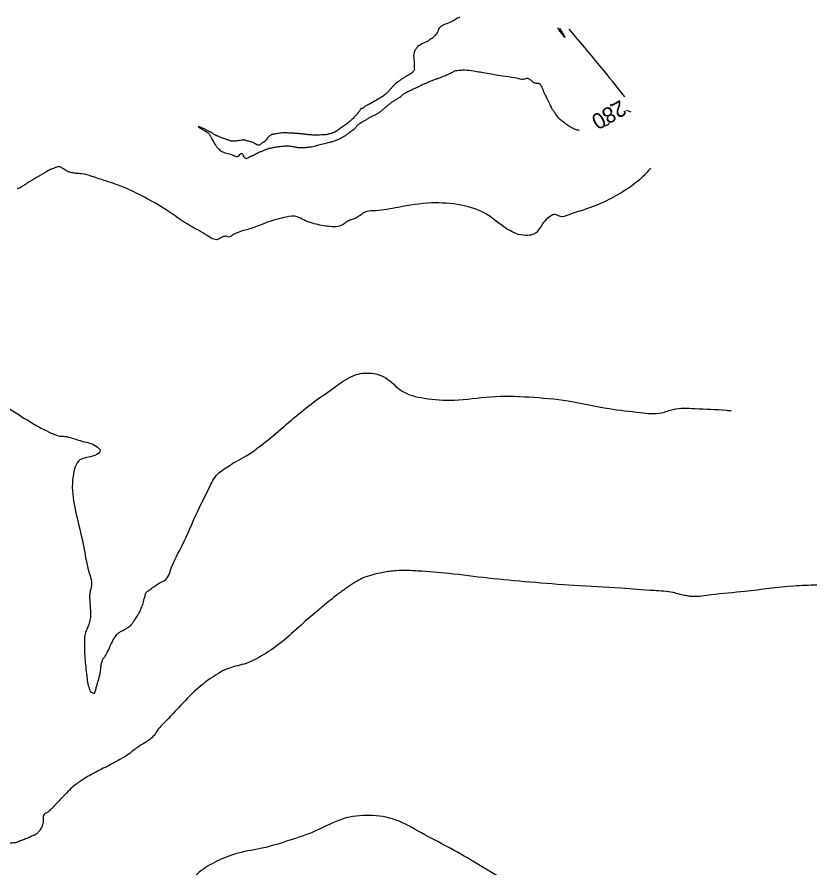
# Model space of a CAD drawing. Extents: x -478102 to -473059, y -1117705 to -1114104.
# Drawn here: x -473729.7 to -473526.4, y -1114945.8 to -1114729.7 of the extents above; entities that cross this region are included whole.
import ezdxf

# ---------------------------------------------------------------- set-up
doc = ezdxf.new("R2010")
doc.units = 0
for name, color, linetype in [('Vrstevnice_hlavni', 7, 'Continuous'), ('Vrstevnice_popis', 7, 'Continuous'), ('Vrstevnice_vedlejsi', 7, 'Continuous')]:
    doc.layers.add(name, color=color, linetype=linetype)

msp = doc.modelspace()

# ---------------------------------------------------------------- linework, layer by layer
at = {"layer": 'Vrstevnice_hlavni'}
msp.add_line((-473574.83, -1114753.395), (-473573.679, -1114753.827), dxfattribs=at)
for points in [[(-473617.201, -1114729.697), (-473620.148, -1114731.265), (-473622.556, -1114732.781), (-473622.788, -1114733.415), (-473623.112, -1114733.992), (-473623.528, -1114734.514), (-473624.036, -1114734.979), (-473624.873, -1114735.541), (-473626.039, -1114736.199), (-473627.533, -1114736.953), (-473628.485, -1114738.067), (-473628.894, -1114739.541), (-473628.762, -1114741.376), (-473628.733, -1114742.663), (-473628.81, -1114743.403), (-473628.991, -1114743.596), (-473629.151, -1114743.75), (-473629.289, -1114743.864), (-473629.405, -1114743.939), (-473629.727, -1114744.134), (-473630.256, -1114744.448), (-473630.99, -1114744.883), (-473631.672, -1114745.321), (-473632.303, -1114745.763), (-473632.882, -1114746.208), (-473633.327, -1114746.553), (-473633.638, -1114746.797), (-473633.816, -1114746.94), (-473634.103, -1114747.235), (-473634.498, -1114747.683), (-473635.003, -1114748.283), (-473635.499, -1114748.811), (-473635.985, -1114749.268), (-473636.461, -1114749.652), (-473637.345, -1114750.232), (-473638.637, -1114751.007), (-473640.337, -1114751.976), (-473641.474, -1114752.622), (-473642.048, -1114752.942), (-473642.058, -1114752.938), (-473642.093, -1114752.94), (-473642.151, -1114752.948), (-473642.234, -1114752.961), (-473642.292, -1114752.989), (-473642.327, -1114753.032), (-473642.336, -1114753.09), (-473642.459, -1114753.28), (-473642.694, -1114753.604), (-473643.042, -1114754.06), (-473643.374, -1114754.477), (-473643.691, -1114754.855), (-473643.992, -1114755.193), (-473644.356, -1114755.56), (-473644.781, -1114755.954), (-473645.268, -1114756.376), (-473645.75, -1114756.766), (-473646.226, -1114757.123), (-473646.697, -1114757.448), (-473647.191, -1114757.792), (-473647.706, -1114758.157), (-473648.243, -1114758.541), (-473648.704, -1114758.835), (-473649.087, -1114759.038), (-473649.394, -1114759.152), (-473649.692, -1114759.255), (-473649.983, -1114759.35), (-473650.264, -1114759.434), (-473650.592, -1114759.51), (-473650.965, -1114759.576)], [(-473591.822, -1114732.544), (-473591.728, -1114732.694), (-473590.442, -1114734.872), (-473591.739, -1114733.259), (-473592.29, -1114732.491)], [(-473575.227, -1114749.998), (-473580.407, -1114743.505), (-473589.357, -1114732.82)], [(-473622.72, -1114745.287), (-473622.568, -1114745.267), (-473622.091, -1114745.085), (-473621.287, -1114744.741), (-473620.158, -1114744.236), (-473619.302, -1114743.843), (-473618.719, -1114743.561), (-473618.41, -1114743.39), (-473617.847, -1114743.267), (-473617.031, -1114743.19), (-473615.96, -1114743.159), (-473613.701, -1114743.412), (-473610.254, -1114743.949), (-473605.617, -1114744.769), (-473602.401, -1114745.262), (-473600.606, -1114745.428), (-473600.23, -1114745.267), (-473599.808, -1114745.309), (-473599.338, -1114745.554), (-473598.82, -1114746.004), (-473598.371, -1114746.307), (-473597.989, -1114746.464), (-473597.675, -1114746.476), (-473597.384, -1114746.515), (-473597.115, -1114746.582), (-473596.868, -1114746.677), (-473596.601, -1114746.996), (-473596.316, -1114747.541), (-473596.011, -1114748.311), (-473595.734, -1114748.977), (-473595.483, -1114749.54), (-473595.26, -1114749.999), (-473595.063, -1114750.394), (-473594.891, -1114750.723), (-473594.745, -1114750.987), (-473594.566, -1114751.348), (-473594.354, -1114751.804), (-473594.108, -1114752.356), (-473593.865, -1114752.833), (-473593.624, -1114753.234), (-473593.384, -1114753.559), (-473593.131, -1114753.922), (-473592.863, -1114754.322), (-473592.581, -1114754.76), (-473592.238, -1114755.177), (-473591.834, -1114755.574), (-473591.368, -1114755.951), (-473590.926, -1114756.299), (-473590.508, -1114756.618), (-473590.113, -1114756.909), (-473589.697, -1114757.196), (-473589.257, -1114757.48), (-473588.796, -1114757.761), (-473588.323, -1114757.996), (-473587.838, -1114758.185), (-473586.846, -1114758.47)], [(-473676.783, -1114764.223), (-473676.119, -1114764.356), (-473675.47, -1114764.542), (-473674.837, -1114764.78), (-473674.219, -1114765.071), (-473673.691, -1114765.115), (-473673.253, -1114764.913), (-473672.904, -1114764.464), (-473672.59, -1114764.373), (-473672.309, -1114764.638), (-473672.062, -1114765.261), (-473671.718, -1114765.581), (-473671.278, -1114765.597), (-473670.741, -1114765.309), (-473670.35, -1114765.113), (-473670.105, -1114765.008), (-473670.006, -1114764.993), (-473669.731, -1114764.869), (-473669.282, -1114764.634), (-473668.656, -1114764.289), (-473668.169, -1114764.046), (-473667.819, -1114763.905), (-473667.608, -1114763.866), (-473667.36, -1114763.78), (-473667.074, -1114763.646), (-473666.752, -1114763.465), (-473666.251, -1114763.277), (-473665.574, -1114763.081), (-473664.719, -1114762.877), (-473663.781, -1114762.708), (-473662.758, -1114762.573), (-473661.652, -1114762.474), (-473660.622, -1114762.476), (-473659.669, -1114762.579), (-473658.793, -1114762.784), (-473657.851, -1114762.887), (-473656.844, -1114762.889), (-473655.772, -1114762.79), (-473654.87, -1114762.665), (-473654.138, -1114762.512), (-473653.576, -1114762.334), (-473652.963, -1114762.161), (-473652.297, -1114761.995), (-473651.579, -1114761.835), (-473650.917, -1114761.68), (-473650.311, -1114761.532), (-473649.76, -1114761.389), (-473649.247, -1114761.234), (-473648.77, -1114761.066), (-473648.331, -1114760.887), (-473647.917, -1114760.71), (-473647.528, -1114760.538), (-473647.164, -1114760.369), (-473646.702, -1114760.098), (-473646.143, -1114759.724), (-473645.485, -1114759.247), (-473644.908, -1114758.83), (-473644.411, -1114758.472), (-473643.995, -1114758.173), (-473643.679, -1114757.89), (-473643.463, -1114757.623), (-473643.349, -1114757.371), (-473643.107, -1114757.105), (-473642.738, -1114756.824), (-473642.242, -1114756.528), (-473641.664, -1114756.186), (-473641.005, -1114755.798), (-473640.265, -1114755.363), (-473639.586, -1114754.988), (-473638.968, -1114754.674), (-473638.412, -1114754.421), (-473637.838, -1114754.081), (-473637.246, -1114753.653), (-473636.637, -1114753.137), (-473636.053, -1114752.645), (-473635.495, -1114752.178), (-473634.963, -1114751.735), (-473634.369, -1114751.3), (-473633.715, -1114750.873), (-473633, -1114750.453), (-473632.41, -1114750.066), (-473631.945, -1114749.71), (-473631.605, -1114749.386), (-473630.997, -1114748.993), (-473630.122, -1114748.53), (-473628.979, -1114747.997), (-473628.097, -1114747.577), (-473627.476, -1114747.27), (-473627.115, -1114747.076), (-473626.486, -1114746.784), (-473625.587, -1114746.396), (-473624.42, -1114745.91), (-473623.599, -1114745.573), (-473623.126, -1114745.385), (-473622.999, -1114745.346), (-473622.864, -1114745.313), (-473622.72, -1114745.287)], [(-473578.381, -1114752.061), (-473578.662, -1114751.956), (-473578.765, -1114751.97), (-473578.83, -1114752.05), (-473578.885, -1114752.345)], [(-473650.965, -1114759.576), (-473651.383, -1114759.634), (-473651.994, -1114759.676), (-473652.795, -1114759.702), (-473653.787, -1114759.712), (-473654.751, -1114759.681), (-473655.684, -1114759.609), (-473656.589, -1114759.495), (-473657.505, -1114759.398), (-473658.433, -1114759.319), (-473659.373, -1114759.256), (-473660.213, -1114759.207), (-473660.954, -1114759.171), (-473661.596, -1114759.148), (-473662.261, -1114759.176), (-473662.95, -1114759.254), (-473663.662, -1114759.382), (-473664.211, -1114759.474), (-473664.597, -1114759.527), (-473664.821, -1114759.543), (-473665.066, -1114759.628), (-473665.331, -1114759.782), (-473665.617, -1114760.006), (-473665.892, -1114760.28), (-473666.155, -1114760.606), (-473666.406, -1114760.982), (-473666.652, -1114761.261), (-473666.893, -1114761.441), (-473667.128, -1114761.523), (-473667.375, -1114761.675), (-473667.634, -1114761.897), (-473667.905, -1114762.189), (-473668.274, -1114762.274), (-473668.742, -1114762.15), (-473669.308, -1114761.818), (-473669.754, -1114761.586), (-473670.08, -1114761.454), (-473670.286, -1114761.423), (-473670.597, -1114761.349), (-473671.014, -1114761.235), (-473671.537, -1114761.078), (-473671.909, -1114760.981), (-473672.13, -1114760.943), (-473672.201, -1114760.964), (-473672.566, -1114761.018), (-473673.227, -1114761.104), (-473674.183, -1114761.222), (-473674.875, -1114761.277), (-473675.303, -1114761.269), (-473675.468, -1114761.198), (-473675.921, -1114761.025), (-473676.662, -1114760.751), (-473677.691, -1114760.374), (-473678.417, -1114760.105), (-473678.841, -1114759.944), (-473678.961, -1114759.891), (-473679.388, -1114759.655), (-473680.121, -1114759.237), (-473681.161, -1114758.636), (-473681.89, -1114758.23), (-473682.31, -1114758.018), (-473682.419, -1114758.001), (-473682.514, -1114757.981), (-473682.595, -1114757.956), (-473682.662, -1114757.928), (-473682.828, -1114757.855), (-473683.093, -1114757.737), (-473683.458, -1114757.573), (-473683.581, -1114757.554), (-473683.46, -1114757.677), (-473683.097, -1114757.944), (-473682.837, -1114758.128), (-473682.679, -1114758.23), (-473682.623, -1114758.249), (-473682.411, -1114758.368), (-473682.042, -1114758.588), (-473681.517, -1114758.908), (-473681.155, -1114759.14), (-473680.954, -1114759.285), (-473680.916, -1114759.341), (-473680.783, -1114759.581), (-473680.555, -1114760.004), (-473680.232, -1114760.61), (-473679.902, -1114761.187), (-473679.566, -1114761.734), (-473679.223, -1114762.253), (-473678.993, -1114762.599), (-473678.878, -1114762.773), (-473678.876, -1114762.776), (-473678.865, -1114762.794), (-473678.846, -1114762.829), (-473678.817, -1114762.88), (-473678.649, -1114763.043), (-473678.342, -1114763.317), (-473677.895, -1114763.703), (-473677.375, -1114764.005), (-473676.783, -1114764.223)], [(-473579.278, -1114756.699), (-473579.351, -1114756.974), (-473579.518, -1114757.108), (-473579.815, -1114757.236), (-473580.671, -1114757.484)]]:
    msp.add_spline(points, degree=3, dxfattribs=at)
at = {"layer": 'Vrstevnice_vedlejsi'}
for points in [[(-473568.69, -1114768.162), (-473571.043, -1114770.634), (-473575.132, -1114773.75), (-473579.905, -1114776.416), (-473585.362, -1114778.63), (-473589.347, -1114779.945), (-473591.862, -1114780.36), (-473592.905, -1114779.876), (-473594.273, -1114780.435), (-473595.965, -1114782.037), (-473597.983, -1114784.684), (-473601.091, -1114785.175), (-473605.29, -1114783.51), (-473610.58, -1114779.69), (-473616.929, -1114777.511), (-473624.339, -1114776.975), (-473632.808, -1114778.08), (-473638.615, -1114778.944), (-473641.761, -1114779.568), (-473642.246, -1114779.95), (-473642.703, -1114780.279), (-473643.132, -1114780.555), (-473643.534, -1114780.777), (-473643.995, -1114780.986), (-473644.513, -1114781.183), (-473645.09, -1114781.367), (-473645.623, -1114781.612), (-473646.113, -1114781.92), (-473646.558, -1114782.289), (-473647.106, -1114782.595), (-473647.757, -1114782.838), (-473648.511, -1114783.017), (-473649.676, -1114783.018), (-473651.251, -1114782.838), (-473653.236, -1114782.48), (-473655.101, -1114781.967), (-473656.843, -1114781.298), (-473658.465, -1114780.475), (-473661.336, -1114780.592), (-473665.457, -1114781.649), (-473670.827, -1114783.646), (-473674.476, -1114784.933), (-473676.404, -1114785.509), (-473676.61, -1114785.376), (-473677.063, -1114785.454), (-473677.763, -1114785.744), (-473678.71, -1114786.246), (-473681.358, -1114785.246), (-473685.706, -1114782.744), (-473691.754, -1114778.74), (-473697.334, -1114775.511), (-473702.447, -1114773.056), (-473707.091, -1114771.377), (-473710.672, -1114770.218), (-473713.19, -1114769.581), (-473714.644, -1114769.465), (-473715.807, -1114769.28), (-473716.677, -1114769.026), (-473717.255, -1114768.703), (-473717.757, -1114768.402), (-473718.184, -1114768.122), (-473718.536, -1114767.864), (-473719.029, -1114767.786), (-473719.663, -1114767.889), (-473720.437, -1114768.173), (-473720.981, -1114768.375), (-473721.295, -1114768.496), (-473721.378, -1114768.536), (-473721.696, -1114768.721), (-473722.249, -1114769.05), (-473723.036, -1114769.524), (-473723.868, -1114770.016), (-473724.745, -1114770.525), (-473725.666, -1114771.052), (-473726.292, -1114771.41), (-473726.623, -1114771.599), (-473726.657, -1114771.619), (-473726.89, -1114771.775), (-473727.321, -1114772.066), (-473727.95, -1114772.492), (-473728.41, -1114772.8), (-473728.702, -1114772.988), (-473728.826, -1114773.056), (-473729.157, -1114773.207), (-473729.696, -1114773.44)], [(-473806.431, -1114819.376), (-473806.381, -1114819.37), (-473806.098, -1114819.332), (-473805.582, -1114819.263), (-473804.834, -1114819.162), (-473804.261, -1114819.077), (-473803.864, -1114819.009), (-473803.644, -1114818.956), (-473803.417, -1114818.893), (-473803.183, -1114818.819), (-473802.943, -1114818.734), (-473802.506, -1114818.567), (-473801.873, -1114818.32), (-473801.043, -1114817.992), (-473800.273, -1114817.659), (-473799.564, -1114817.322), (-473798.915, -1114816.98), (-473798.152, -1114816.622), (-473797.275, -1114816.247), (-473796.283, -1114815.855), (-473795.349, -1114815.355), (-473794.472, -1114814.747), (-473793.652, -1114814.031), (-473792.884, -1114813.394), (-473792.169, -1114812.838), (-473791.505, -1114812.362), (-473790.848, -1114811.926), (-473790.199, -1114811.529), (-473789.558, -1114811.173), (-473789.109, -1114810.813), (-473788.855, -1114810.448), (-473788.794, -1114810.078), (-473788.776, -1114809.715), (-473788.799, -1114809.357), (-473788.866, -1114809.005), (-473788.918, -1114808.758), (-473788.957, -1114808.615), (-473788.983, -1114808.577), (-473789.064, -1114808.473), (-473789.201, -1114808.304), (-473789.395, -1114808.069), (-473789.377, -1114807.652), (-473789.15, -1114807.051), (-473788.711, -1114806.268), (-473788.347, -1114805.792), (-473788.056, -1114805.624), (-473787.84, -1114805.764), (-473787.626, -1114805.871), (-473787.415, -1114805.946), (-473787.208, -1114805.988), (-473786.496, -1114806.071), (-473785.282, -1114806.195), (-473783.563, -1114806.36), (-473781.602, -1114806.318), (-473779.398, -1114806.068), (-473776.952, -1114805.611), (-473775.18, -1114805.346), (-473774.082, -1114805.272), (-473773.659, -1114805.389), (-473771.906, -1114806.017), (-473768.824, -1114807.156), (-473764.412, -1114808.805), (-473757.986, -1114812.228), (-473749.545, -1114817.424), (-473739.091, -1114824.394), (-473731.162, -1114829.574), (-473725.758, -1114832.963), (-473722.879, -1114834.562), (-473720.556, -1114835.651), (-473718.788, -1114836.229), (-473717.576, -1114836.296), (-473715.636, -1114836.745), (-473712.97, -1114837.576), (-473709.576, -1114838.788), (-473708.568, -1114839.978), (-473709.947, -1114841.147), (-473713.712, -1114842.295), (-473715.457, -1114846.434), (-473715.18, -1114853.565), (-473712.883, -1114863.688), (-473711.435, -1114870.722), (-473710.835, -1114874.668), (-473711.083, -1114875.525), (-473711.225, -1114876.407), (-473711.259, -1114877.314), (-473711.187, -1114878.247), (-473711.116, -1114879.28), (-473711.047, -1114880.415), (-473710.98, -1114881.651), (-473711.162, -1114883.025), (-473711.593, -1114884.537), (-473712.273, -1114886.186), (-473712.575, -1114888.746), (-473712.5, -1114892.217), (-473712.048, -1114896.598), (-473711.581, -1114899.59), (-473711.1, -1114901.193)], [(-473711.1, -1114901.193), (-473710.605, -1114901.408), (-473710.258, -1114901.535), (-473710.058, -1114901.575), (-473710.007, -1114901.528), (-473709.97, -1114901.492), (-473709.947, -1114901.468), (-473709.939, -1114901.455), (-473709.933, -1114901.443), (-473709.93, -1114901.43), (-473709.929, -1114901.418), (-473709.776, -1114900.891), (-473709.47, -1114899.849), (-473709.012, -1114898.292), (-473708.706, -1114897.237), (-473708.552, -1114896.685), (-473708.55, -1114896.636), (-473708.503, -1114896.233), (-473708.411, -1114895.476), (-473708.274, -1114894.367), (-473708.061, -1114893.473), (-473707.77, -1114892.795), (-473707.402, -1114892.333), (-473706.942, -1114891.554), (-473706.388, -1114890.459), (-473705.742, -1114889.047), (-473705.176, -1114887.943), (-473704.691, -1114887.145), (-473704.287, -1114886.654), (-473703.727, -1114886.179), (-473703.009, -1114885.72), (-473702.135, -1114885.277), (-473701.429, -1114884.844), (-473700.892, -1114884.421), (-473700.524, -1114884.007), (-473700.056, -1114883.379), (-473699.486, -1114882.538), (-473698.816, -1114881.483), (-473698.239, -1114880.312), (-473697.755, -1114879.025), (-473697.365, -1114877.622), (-473697.09, -1114876.652), (-473696.929, -1114876.116), (-473696.884, -1114876.013), (-473696.495, -1114875.687), (-473695.763, -1114875.139), (-473694.687, -1114874.368), (-473693.741, -1114873.74), (-473692.922, -1114873.256), (-473692.232, -1114872.914), (-473690.49, -1114869.833), (-473687.695, -1114864.012), (-473683.847, -1114855.451), (-473680.855, -1114849.406), (-473678.717, -1114845.877), (-473677.433, -1114844.863), (-473675.793, -1114843.76), (-473673.797, -1114842.567), (-473671.444, -1114841.283), (-473668.135, -1114838.936), (-473663.869, -1114835.524), (-473658.648, -1114831.049), (-473653.675, -1114827.133), (-473648.951, -1114823.776), (-473644.476, -1114820.979), (-473640.154, -1114820.201), (-473635.987, -1114821.442), (-473631.975, -1114824.702), (-473626.193, -1114826.584), (-473618.642, -1114827.089), (-473609.321, -1114826.215), (-473599.642, -1114826.282), (-473589.604, -1114827.29), (-473579.207, -1114829.24), (-473571.298, -1114830.245), (-473565.874, -1114830.308), (-473562.937, -1114829.427), (-473557.455, -1114829.209), (-473549.427, -1114829.656), (-473548.186, -1114829.776)], [(-473526.395, -1114874.113), (-473532.359, -1114874.36), (-473544.718, -1114875.726), (-473553.283, -1114876.606), (-473558.052, -1114876.999), (-473559.026, -1114876.906), (-473560.162, -1114876.711), (-473561.461, -1114876.414), (-473562.922, -1114876.015), (-473567.854, -1114875.517), (-473576.255, -1114874.919), (-473588.128, -1114874.22), (-473599.375, -1114873.362), (-473609.998, -1114872.346), (-473619.995, -1114871.169), (-473627.772, -1114870.537), (-473633.329, -1114870.448), (-473636.664, -1114870.903), (-473639.509, -1114871.545), (-473641.864, -1114872.374), (-473643.728, -1114873.391), (-473645.758, -1114874.69), (-473647.953, -1114876.272), (-473650.314, -1114878.136), (-473653.501, -1114880.802), (-473657.514, -1114884.269), (-473662.353, -1114888.539), (-473667.002, -1114891.784), (-473671.461, -1114894.004), (-473675.731, -1114895.199), (-473680.102, -1114897.564), (-473684.576, -1114901.098), (-473689.152, -1114905.802), (-473692.364, -1114909.206), (-473694.211, -1114911.309), (-473694.695, -1114912.113), (-473695.459, -1114912.918), (-473696.503, -1114913.724), (-473697.827, -1114914.532), (-473699.075, -1114915.363), (-473700.246, -1114916.217), (-473701.341, -1114917.094), (-473703.362, -1114918.336), (-473706.309, -1114919.942), (-473710.181, -1114921.913), (-473713.274, -1114923.746), (-473715.589, -1114925.44), (-473717.126, -1114926.997), (-473718.478, -1114928.387), (-473719.646, -1114929.609), (-473720.629, -1114930.664), (-473721.457, -1114931.458), (-473722.128, -1114931.991), (-473722.644, -1114932.262), (-473722.962, -1114932.678), (-473723.083, -1114933.239), (-473723.006, -1114933.945), (-473723.114, -1114934.706), (-473723.407, -1114935.522), (-473723.884, -1114936.394), (-473724.434, -1114937.07), (-473725.058, -1114937.55), (-473725.755, -1114937.833), (-473726.283, -1114938.062), (-473726.64, -1114938.235), (-473726.826, -1114938.354), (-473727.213, -1114938.528), (-473727.8, -1114938.757), (-473728.586, -1114939.042), (-473729.182, -1114939.264), (-473729.586, -1114939.425), (-473729.8, -1114939.524), (-473730.254, -1114939.616), (-473730.95, -1114939.702), (-473731.886, -1114939.78), (-473732.59, -1114939.885), (-473733.063, -1114940.018), (-473733.303, -1114940.178), (-473733.526, -1114940.372), (-473733.733, -1114940.6), (-473733.922, -1114940.863), (-473734.063, -1114941.144), (-473734.157, -1114941.443)], [(-473561.156, -1115040.646), (-473558.781, -1115037.213), (-473557.187, -1115034.901), (-473556.372, -1115033.711), (-473556.338, -1115033.643), (-473556.311, -1115033.59), (-473556.293, -1115033.552), (-473556.283, -1115033.528), (-473556.279, -1115033.511), (-473556.281, -1115033.5), (-473556.289, -1115033.495), (-473556.421, -1115033.377), (-473556.677, -1115033.145), (-473557.057, -1115032.799), (-473557.62, -1115032.315), (-473558.366, -1115031.693), (-473559.296, -1115030.931), (-473560.566, -1115030.342), (-473562.177, -1115029.923), (-473564.129, -1115029.676), (-473566.903, -1115026.241), (-473570.501, -1115019.619), (-473574.922, -1115009.809), (-473579.042, -1114999.948), (-473582.86, -1114990.035), (-473586.377, -1114980.071), (-473588.815, -1114972.305), (-473590.174, -1114966.738), (-473590.455, -1114963.369), (-473591.672, -1114960.299), (-473593.824, -1114957.53), (-473596.912, -1114955.059), (-473601.234, -1114952.054), (-473606.789, -1114948.515), (-473613.579, -1114944.442), (-473620.286, -1114940.635), (-473626.912, -1114937.096), (-473633.456, -1114933.824), (-473640.095, -1114932.638), (-473646.829, -1114933.539), (-473653.657, -1114936.527), (-473660.378, -1114938.975), (-473666.99, -1114940.884), (-473673.495, -1114942.253), (-473678.952, -1114944.323), (-473683.362, -1114947.092), (-473686.723, -1114950.561), (-473689.03, -1114952.941), (-473690.281, -1114954.233), (-473690.477, -1114954.435), (-473692.879, -1114955.166), (-473697.488, -1114956.426), (-473704.302, -1114958.213), (-473709.527, -1114959.686), (-473713.161, -1114960.844), (-473715.205, -1114961.689), (-473716.721, -1114962.296), (-473717.709, -1114962.665), (-473718.169, -1114962.797), (-473718.696, -1114962.786), (-473719.289, -1114962.633), (-473719.949, -1114962.336), (-473720.59, -1114962.131), (-473721.213, -1114962.016), (-473721.818, -1114961.992), (-473723.59, -1114961.904), (-473726.531, -1114961.751), (-473730.64, -1114961.534), (-473733.445, -1114961.489), (-473734.948, -1114961.615), (-473735.148, -1114961.913), (-473735.368, -1114962.161), (-473735.608, -1114962.359), (-473735.869, -1114962.506), (-473736.071, -1114962.787), (-473736.212, -1114963.202), (-473736.294, -1114963.751), (-473736.593, -1114964.127), (-473737.109, -1114964.332), (-473737.841, -1114964.364), (-473738.81, -1114964.474), (-473740.014, -1114964.661), (-473741.454, -1114964.925), (-473742.993, -1114965.301), (-473744.633, -1114965.788), (-473746.372, -1114966.387), (-473747.696, -1114966.833), (-473748.605, -1114967.126), (-473749.099, -1114967.264), (-473749.791, -1114967.567), (-473750.681, -1114968.032), (-473751.769, -1114968.661), (-473752.634, -1114969.122), (-473753.277, -1114969.414), (-473753.696, -1114969.539), (-473754.241, -1114969.757), (-473754.912, -1114970.069)]]:
    msp.add_spline(points, degree=3, dxfattribs=at)

# ---------------------------------------------------------------- texts
at = {"layer": 'Vrstevnice_popis'}
msp.add_text(' 280 ', height=4, rotation=209.39952, dxfattribs=at).set_placement((-473575.028, -1114749.942))

doc.saveas('drawing.dxf')
